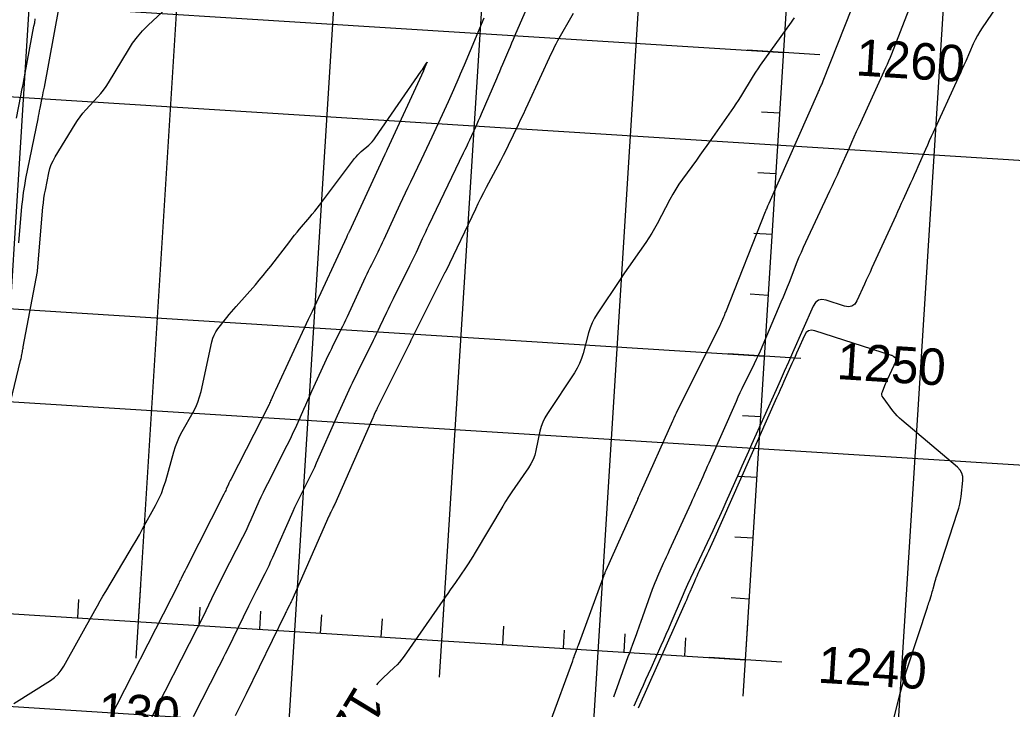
# Model space of a CAD drawing. Extents: x 658976 to 668721, y 639543 to 647196.
# Drawn here: x 661779.9 to 661943.1, y 641892.5 to 642005.8 of the extents above; entities that cross this region are included whole.
import ezdxf

# ---------------------------------------------------------------- set-up
doc = ezdxf.new("R2010")
doc.units = 0
for name, color, linetype in [('Ex_Contour Labels', 7, 'Continuous'), ('Ex_Major Contours', 7, 'Continuous'), ('Ex_Minor Contours', 7, 'Continuous'), ('R_Axis', 7, 'Continuous'), ('R_Axis Annot', 7, 'Continuous'), ('R_Grid', 7, 'Continuous')]:
    doc.layers.add(name, color=color, linetype=linetype)

msp = doc.modelspace()

# ---------------------------------------------------------------- linework, layer by layer
at = {"layer": 'Ex_Major Contours'}
for points in [[(661867.15, 641890.47), (661870.82, 641900.42), (661870.9, 641900.63), (661870.97, 641900.85), (661871.05, 641901.06), (661871.13, 641901.28), (661871.44, 641902.13), (661871.51, 641902.35), (661871.59, 641902.56), (661871.67, 641902.77), (661871.75, 641902.99), (661875.84, 641914.07), (661875.88, 641914.18), (661875.92, 641914.28), (661875.96, 641914.39), (661875.99, 641914.5), (661876.14, 641914.92), (661876.18, 641915.03), (661876.22, 641915.13), (661876.27, 641915.23), (661876.31, 641915.34), (661881.45, 641926.84), (661881.5, 641926.96), (661881.55, 641927.08), (661881.61, 641927.2), (661881.66, 641927.32), (661881.88, 641927.79), (661881.93, 641927.91), (661881.99, 641928.03), (661882.04, 641928.14), (661882.09, 641928.26), (661887.27, 641939.88), (661887.33, 641940), (661887.38, 641940.12), (661887.44, 641940.24), (661887.49, 641940.36), (661887.7, 641940.85), (661887.76, 641940.97), (661887.81, 641941.09), (661887.87, 641941.21), (661887.93, 641941.33), (661894.98, 641955.41), (661895.07, 641955.6), (661895.16, 641955.79), (661895.25, 641955.99), (661895.33, 641956.18), (661895.66, 641956.96), (661895.75, 641957.16), (661895.83, 641957.35), (661895.91, 641957.55), (661895.99, 641957.74), (661902.51, 641974.26), (661902.55, 641974.38), (661902.6, 641974.5), (661902.65, 641974.61), (661902.71, 641974.73), (661902.92, 641975.19), (661902.97, 641975.3), (661903.03, 641975.41), (661903.08, 641975.53), (661903.13, 641975.65), (661911.18, 641993.86), (661911.25, 641994.01), (661911.32, 641994.17), (661911.39, 641994.33), (661911.46, 641994.48), (661911.75, 641995.1), (661911.82, 641995.26), (661911.89, 641995.41), (661911.95, 641995.57), (661912.02, 641995.73), (661917.97, 642010.88)], [(661907.21, 642006.13), (661906.98, 642005.74), (661906.73, 642005.38), (661901.65, 641998.3), (661901.26, 641997.74), (661900.88, 641997.18), (661900.51, 641996.6), (661900.15, 641996.02), (661898.75, 641993.68), (661898.4, 641993.1), (661898.03, 641992.52), (661897.65, 641991.95), (661897.27, 641991.39), (661893.42, 641985.9), (661892.86, 641985.1), (661892.29, 641984.31), (661891.72, 641983.52), (661891.15, 641982.73), (661888.85, 641979.58), (661888.29, 641978.78), (661887.76, 641977.96), (661887.26, 641977.13), (661886.8, 641976.27), (661884.69, 641972.26), (661884.26, 641971.47), (661883.8, 641970.7), (661883.32, 641969.94), (661882.82, 641969.19), (661880.75, 641966.24), (661880.24, 641965.5), (661879.73, 641964.75), (661879.22, 641964.01), (661878.71, 641963.26), (661874.83, 641957.47), (661874.38, 641956.73), (661873.99, 641955.96), (661873.67, 641955.16), (661873.41, 641954.32), (661872.52, 641950.93), (661872.27, 641950.1), (661871.95, 641949.3), (661871.56, 641948.52), (661871.11, 641947.78), (661866.65, 641941.07), (661866.24, 641940.39), (661865.9, 641939.67), (661865.63, 641938.93), (661865.43, 641938.16), (661864.77, 641935.02), (661864.57, 641934.25), (661864.3, 641933.51), (661863.95, 641932.8), (661863.53, 641932.13), (661861.29, 641928.93), (661860.78, 641928.18), (661860.27, 641927.41), (661859.78, 641926.64), (661859.31, 641925.85), (661854.78, 641918.23), (661854.4, 641917.6), (661854, 641916.97), (661853.6, 641916.35), (661853.19, 641915.74), (661851.52, 641913.3), (661851.1, 641912.69), (661850.68, 641912.09), (661850.26, 641911.48), (661849.84, 641910.87), (661843.11, 641901.19), (661842.74, 641900.69), (661842.35, 641900.22), (661841.93, 641899.76), (661841.48, 641899.33), (661839.64, 641897.66), (661839.2, 641897.22), (661838.79, 641896.76), (661838.58, 641896.47)], [(661923.17, 641889.22), (661924.65, 641895.06), (661924.97, 641896.26), (661925.3, 641897.44), (661925.66, 641898.63), (661926.03, 641899.8), (661929.13, 641909.25), (661929.21, 641909.5), (661929.29, 641909.75), (661929.38, 641910.01), (661929.46, 641910.26), (661929.79, 641911.27), (661929.87, 641911.52), (661929.94, 641911.78), (661930.02, 641912.03), (661930.09, 641912.29), (661930.43, 641913.54), (661930.52, 641913.83), (661930.6, 641914.13), (661930.69, 641914.42), (661930.78, 641914.71), (661934.11, 641924.89), (661934.3, 641925.52), (661934.45, 641926.16), (661934.58, 641926.8), (661934.67, 641927.46), (661934.96, 641930.08), (661934.96, 641930.7), (661934.82, 641931.27), (661934.53, 641931.78), (661934.1, 641932.24), (661924.95, 641939.96), (661924.55, 641940.32), (661924.17, 641940.7), (661923.81, 641941.1), (661923.47, 641941.53), (661921.85, 641943.69), (661921.72, 641943.92), (661921.66, 641944.15), (661921.66, 641944.4), (661921.73, 641944.65), (661922.15, 641945.67), (661922.26, 641945.93), (661922.37, 641946.18), (661922.48, 641946.44), (661922.59, 641946.69), (661924.01, 641949.75), (661924.04, 641949.85), (661924.04, 641949.94), (661924, 641950.03), (661923.94, 641950.11), (661923.6, 641950.41), (661923.51, 641950.48), (661923.42, 641950.54), (661923.32, 641950.59), (661923.21, 641950.62), (661910.63, 641954.66), (661910.07, 641954.75), (661909.6, 641954.66), (661909.21, 641954.37), (661908.92, 641953.89), (661907.89, 641951.58), (661907.64, 641951.01), (661907.38, 641950.43), (661907.13, 641949.85), (661906.87, 641949.28), (661905.55, 641946.35), (661905.25, 641945.67), (661904.94, 641944.99), (661904.64, 641944.31), (661904.34, 641943.63), (661893.97, 641920.26), (661893.7, 641919.66), (661893.43, 641919.07), (661893.16, 641918.48), (661892.88, 641917.89), (661891.61, 641915.21), (661891.41, 641914.78), (661891.21, 641914.35), (661891.02, 641913.91), (661890.83, 641913.48), (661890.07, 641911.73), (661889.88, 641911.3), (661889.69, 641910.86), (661889.5, 641910.42), (661889.31, 641909.99), (661881.58, 641892.67)]]:
    msp.add_lwpolyline(points, dxfattribs=at)
at = {"layer": 'Ex_Minor Contours'}
for points in [[(661776.99, 641937.25), (661780.04, 641949.77), (661780.08, 641949.96), (661780.12, 641950.14), (661780.16, 641950.33), (661780.2, 641950.52), (661780.33, 641951.27), (661780.37, 641951.45), (661780.4, 641951.64), (661780.44, 641951.83), (661780.47, 641952.01), (661782.82, 641964.43), (661782.83, 641964.45), (661782.83, 641964.47), (661782.83, 641964.49), (661782.84, 641964.5), (661783.72, 641974.98), (661783.79, 641975.69), (661783.88, 641976.4), (661783.99, 641977.11), (661784.13, 641977.81), (661784.69, 641980.63), (661784.87, 641981.32), (661785.09, 641981.99), (661785.38, 641982.63), (661785.72, 641983.26), (661789, 641988.63), (661789.39, 641989.25), (661789.82, 641989.84), (661790.27, 641990.41), (661790.75, 641990.96), (661792.74, 641993.11), (661793.23, 641993.66), (661793.68, 641994.23), (661794.1, 641994.83), (661794.5, 641995.44), (661797.76, 642000.87), (661798.46, 642001.96), (661799.24, 642002.99), (661800.08, 642003.96), (661800.99, 642004.88), (661808.68, 642012.07)], [(661863.69, 642008.72), (661861.27, 642003.11), (661861.02, 642002.52), (661860.77, 642001.94), (661860.52, 642001.35), (661860.27, 642000.76), (661859.27, 641998.41), (661859.02, 641997.82), (661858.77, 641997.23), (661858.52, 641996.65), (661858.27, 641996.06), (661855.76, 641990.26), (661855.53, 641989.72), (661855.29, 641989.19), (661855.05, 641988.65), (661854.81, 641988.12), (661853.82, 641985.99), (661853.58, 641985.45), (661853.33, 641984.92), (661853.08, 641984.39), (661852.83, 641983.86), (661847.12, 641971.96), (661846.85, 641971.41), (661846.59, 641970.86), (661846.34, 641970.31), (661846.08, 641969.76), (661845.06, 641967.55), (661844.8, 641967), (661844.54, 641966.45), (661844.27, 641965.9), (661844, 641965.36), (661841.29, 641959.95), (661841.01, 641959.38), (661840.73, 641958.81), (661840.46, 641958.23), (661840.19, 641957.66), (661839.12, 641955.36), (661838.85, 641954.78), (661838.58, 641954.21), (661838.3, 641953.64), (661838.02, 641953.07), (661835.42, 641947.87), (661835.13, 641947.28), (661834.84, 641946.69), (661834.56, 641946.09), (661834.28, 641945.5), (661833.17, 641943.11), (661832.89, 641942.51), (661832.62, 641941.91), (661832.35, 641941.31), (661832.09, 641940.71), (661828.64, 641932.89), (661828.34, 641932.22), (661828.03, 641931.55), (661827.71, 641930.89), (661827.38, 641930.24), (661826.05, 641927.62), (661825.72, 641926.97), (661825.4, 641926.3), (661825.09, 641925.64), (661824.79, 641924.97), (661821.46, 641917.42), (661821.15, 641916.74), (661820.83, 641916.06), (661820.51, 641915.39), (661820.17, 641914.72), (661818.82, 641912.06), (661818.48, 641911.4), (661818.15, 641910.73), (661817.82, 641910.06), (661817.49, 641909.39), (661814.03, 641902.29), (661813.69, 641901.59), (661813.34, 641900.9), (661813, 641900.2), (661812.64, 641899.51), (661808.43, 641891.24)], [(661941.31, 642009.17), (661938.14, 642004.48), (661937.73, 642003.84), (661937.35, 642003.18), (661936.99, 642002.51), (661936.67, 642001.81), (661935.44, 641999.01), (661935.13, 641998.31), (661934.82, 641997.61), (661934.51, 641996.91), (661934.19, 641996.22), (661930.08, 641987.27), (661929.76, 641986.58), (661929.45, 641985.88), (661929.14, 641985.18), (661928.83, 641984.48), (661927.57, 641981.61), (661927.28, 641980.94), (661926.98, 641980.27), (661926.67, 641979.6), (661926.37, 641978.93), (661925.14, 641976.25), (661924.84, 641975.58), (661924.53, 641974.91), (661924.23, 641974.24), (661923.92, 641973.57), (661920.01, 641965), (661919.7, 641964.33), (661919.4, 641963.66), (661919.09, 641962.98), (661918.78, 641962.31), (661917.55, 641959.62), (661917.19, 641959.05), (661916.73, 641958.72), (661916.18, 641958.61), (661915.52, 641958.72), (661912.49, 641959.69), (661911.8, 641959.81), (661911.22, 641959.69), (661910.75, 641959.34), (661910.38, 641958.74), (661906.97, 641951.03), (661906.29, 641949.51), (661905.61, 641947.99), (661904.94, 641946.47), (661904.26, 641944.95), (661900.23, 641935.99), (661899.7, 641934.81), (661899.18, 641933.62), (661898.65, 641932.44), (661898.12, 641931.26), (661896.02, 641926.52), (661895.49, 641925.34), (661894.95, 641924.16), (661894.41, 641922.98), (661893.86, 641921.81), (661890.65, 641915.04), (661890.18, 641914.03), (661889.71, 641913), (661889.25, 641911.98), (661888.8, 641910.95), (661886.94, 641906.63), (661886.54, 641905.7), (661886.13, 641904.76), (661885.72, 641903.83), (661885.3, 641902.9), (661883.64, 641899.18), (661883.22, 641898.25), (661882.81, 641897.31), (661882.39, 641896.38), (661881.97, 641895.45), (661880.87, 641892.99)], [(661779.76, 641969.13), (661780.26, 641975.08), (661780.38, 641976.25), (661780.52, 641977.4), (661780.71, 641978.56), (661780.92, 641979.7), (661782.91, 641989.51), (661782.99, 641989.94), (661783.08, 641990.37), (661783.17, 641990.81), (661783.25, 641991.24), (661783.6, 641992.98), (661783.69, 641993.41), (661783.77, 641993.85), (661783.86, 641994.28), (661783.94, 641994.72), (661786.35, 642007.56)], [(661870.88, 642006.84), (661868.34, 642002.31), (661868.06, 642001.8), (661867.79, 642001.28), (661867.53, 642000.76), (661867.28, 642000.23), (661863.45, 641991.93), (661863.06, 641991.07), (661862.66, 641990.22), (661862.25, 641989.37), (661861.85, 641988.53), (661860.21, 641985.14), (661859.8, 641984.3), (661859.38, 641983.46), (661858.95, 641982.62), (661858.51, 641981.79), (661856.6, 641978.2), (661856.14, 641977.32), (661855.68, 641976.44), (661855.24, 641975.55), (661854.81, 641974.66), (661849.93, 641964.49), (661849.92, 641964.47), (661849.91, 641964.45), (661849.9, 641964.43), (661849.89, 641964.4), (661849.85, 641964.31), (661849.84, 641964.29), (661849.83, 641964.27), (661849.82, 641964.25), (661849.81, 641964.23), (661844.32, 641953.29), (661844.28, 641953.22), (661844.24, 641953.14), (661844.21, 641953.06), (661844.17, 641952.98), (661844.02, 641952.66), (661843.98, 641952.58), (661843.95, 641952.5), (661843.91, 641952.42), (661843.87, 641952.34), (661838.66, 641941.93), (661838.6, 641941.8), (661838.54, 641941.67), (661838.47, 641941.54), (661838.41, 641941.41), (661838.17, 641940.89), (661838.11, 641940.76), (661838.05, 641940.62), (661837.99, 641940.49), (661837.93, 641940.36), (661831.68, 641926.17), (661831.61, 641926.01), (661831.53, 641925.84), (661831.45, 641925.68), (661831.37, 641925.52), (661831.04, 641924.87), (661830.96, 641924.7), (661830.88, 641924.54), (661830.8, 641924.38), (661830.73, 641924.21), (661824.61, 641910.34), (661824.52, 641910.15), (661824.44, 641909.97), (661824.35, 641909.78), (661824.25, 641909.6), (661823.88, 641908.87), (661823.79, 641908.68), (661823.7, 641908.5), (661823.61, 641908.32), (661823.52, 641908.13), (661817.13, 641895.02), (661817.02, 641894.79), (661816.91, 641894.56), (661816.79, 641894.34), (661816.68, 641894.11), (661815.3, 641891.41)], [(661877.57, 641894.49), (661879.96, 641901.14), (661880.13, 641901.62), (661880.3, 641902.09), (661880.48, 641902.56), (661880.65, 641903.03), (661881.35, 641904.92), (661881.52, 641905.39), (661881.69, 641905.87), (661881.86, 641906.34), (661882.03, 641906.81), (661883.95, 641912.19), (661884.15, 641912.74), (661884.37, 641913.28), (661884.59, 641913.82), (661884.82, 641914.36), (661885.77, 641916.49), (661886.01, 641917.02), (661886.25, 641917.55), (661886.49, 641918.09), (661886.73, 641918.62), (661890.28, 641926.32), (661890.53, 641926.87), (661890.78, 641927.43), (661891.03, 641927.98), (661891.28, 641928.53), (661892.26, 641930.74), (661892.51, 641931.29), (661892.75, 641931.85), (661893, 641932.4), (661893.24, 641932.95), (661897.73, 641943.12), (661898.04, 641943.82), (661898.36, 641944.51), (661898.69, 641945.2), (661899.03, 641945.88), (661900.4, 641948.61), (661900.73, 641949.3), (661901.06, 641949.99), (661901.37, 641950.68), (661901.68, 641951.38), (661905.11, 641959.43), (661905.45, 641960.24), (661905.79, 641961.06), (661906.12, 641961.87), (661906.45, 641962.69), (661907.74, 641965.98), (661908.07, 641966.8), (661908.42, 641967.61), (661908.77, 641968.42), (661909.14, 641969.22), (661913.12, 641977.68), (661913.53, 641978.56), (661913.93, 641979.44), (661914.33, 641980.33), (661914.73, 641981.21), (661916.3, 641984.76), (661916.69, 641985.65), (661917.09, 641986.53), (661917.49, 641987.42), (661917.89, 641988.3), (661922.31, 641997.93), (661922.57, 641998.49), (661922.82, 641999.06), (661923.05, 641999.64), (661923.29, 642000.21), (661926.15, 642007.51)], [(661779.34, 641989.61), (661780.08, 641993.31), (661780.26, 641994.24), (661780.44, 641995.17), (661780.62, 641996.09), (661780.8, 641997.02), (661782.24, 642004.71), (661782.35, 642005.31), (661782.44, 642005.92)], [(661856.22, 642006.03), (661852.96, 641998.34), (661852.75, 641997.83), (661852.53, 641997.33), (661852.31, 641996.82), (661852.1, 641996.32), (661851.22, 641994.29), (661851, 641993.79), (661850.78, 641993.28), (661850.55, 641992.78), (661850.33, 641992.28), (661847.65, 641986.48), (661847.22, 641985.55), (661846.79, 641984.63), (661846.35, 641983.71), (661845.91, 641982.79), (661844.15, 641979.12), (661843.71, 641978.2), (661843.28, 641977.27), (661842.84, 641976.35), (661842.41, 641975.43), (661839.75, 641969.67), (661839.51, 641969.15), (661839.26, 641968.62), (661839.01, 641968.1), (661838.75, 641967.59), (661837.71, 641965.52), (661837.46, 641965), (661837.2, 641964.48), (661836.96, 641963.96), (661836.71, 641963.44), (661833.72, 641956.98), (661833.47, 641956.44), (661833.22, 641955.91), (661832.96, 641955.39), (661832.7, 641954.86), (661831.65, 641952.76), (661831.39, 641952.24), (661831.14, 641951.71), (661830.88, 641951.18), (661830.63, 641950.65), (661827.87, 641944.69), (661827.53, 641943.95), (661827.19, 641943.21), (661826.86, 641942.46), (661826.53, 641941.72), (661825.21, 641938.74), (661824.88, 641937.99), (661824.54, 641937.26), (661824.18, 641936.52), (661823.82, 641935.8), (661820.62, 641929.53), (661820.26, 641928.81), (661819.91, 641928.07), (661819.56, 641927.34), (661819.23, 641926.6), (661817.92, 641923.63), (661817.59, 641922.89), (661817.24, 641922.15), (661816.89, 641921.42), (661816.53, 641920.7), (661813.31, 641914.38), (661812.95, 641913.67), (661812.59, 641912.96), (661812.24, 641912.25), (661811.89, 641911.53), (661810.49, 641908.66), (661810.14, 641907.94), (661809.79, 641907.23), (661809.43, 641906.52), (661809.07, 641905.8), (661801.13, 641890.23)], [(661778.94, 641893.42), (661784.93, 641897.21), (661785.6, 641897.7), (661786.2, 641898.25), (661786.72, 641898.88), (661787.17, 641899.58), (661792.24, 641908.71), (661792.67, 641909.49), (661793.12, 641910.27), (661793.57, 641911.04), (661794.03, 641911.82), (661797.9, 641918.29), (661798.46, 641919.24), (661799.02, 641920.19), (661799.56, 641921.15), (661800.1, 641922.11), (661802.23, 641925.96), (661802.73, 641926.94), (661803.18, 641927.94), (661803.56, 641928.96), (661803.89, 641930.01), (661805.22, 641934.76), (661805.49, 641935.63), (661805.81, 641936.48), (661806.19, 641937.31), (661806.61, 641938.12), (661808.41, 641941.31), (661808.83, 641942.12), (661809.18, 641942.96), (661809.47, 641943.82), (661809.7, 641944.7), (661811.49, 641952.88), (661811.65, 641953.44), (661811.86, 641953.98), (661812.14, 641954.5), (661812.48, 641954.98), (661813.96, 641956.86), (661814.33, 641957.33), (661814.71, 641957.79), (661815.09, 641958.24), (661815.49, 641958.69), (661818.64, 641962.25), (661819.29, 641962.99), (661819.93, 641963.75), (661820.55, 641964.52), (661821.16, 641965.3), (661824.29, 641969.37), (661824.68, 641969.88), (661825.09, 641970.38), (661825.49, 641970.88), (661825.91, 641971.37), (661827.59, 641973.32), (661828, 641973.82), (661828.41, 641974.31), (661828.81, 641974.82), (661829.2, 641975.33), (661834.95, 641982.96), (661835.2, 641983.28), (661835.47, 641983.58), (661835.75, 641983.86), (661836.05, 641984.13), (661837.28, 641985.19), (661837.57, 641985.46), (661837.85, 641985.75), (661838.11, 641986.05), (661838.35, 641986.38), (661845.9, 641997.35), (661845.92, 641997.38), (661845.93, 641997.4), (661845.95, 641997.42), (661845.97, 641997.44), (661846.05, 641997.52), (661846.07, 641997.54), (661846.09, 641997.56), (661846.1, 641997.58), (661846.12, 641997.6), (661846.75, 641998.65), (661846.83, 641998.79), (661846.87, 641998.83), (661846.86, 641998.78), (661846.8, 641998.63), (661846.3, 641997.43), (661846.29, 641997.41), (661846.28, 641997.39), (661846.27, 641997.37), (661840.33, 641984.49), (661840.29, 641984.41), (661840.26, 641984.33), (661840.22, 641984.25), (661840.18, 641984.17), (661840.03, 641983.85), (661839.99, 641983.77), (661839.95, 641983.69), (661839.91, 641983.61), (661839.88, 641983.53), (661834.07, 641970.96), (661834.03, 641970.88), (661833.99, 641970.8), (661833.95, 641970.72), (661833.91, 641970.64), (661833.75, 641970.32), (661833.71, 641970.24), (661833.67, 641970.16), (661833.64, 641970.08), (661833.6, 641970), (661827.97, 641957.84), (661827.92, 641957.73), (661827.86, 641957.62), (661827.81, 641957.51), (661827.76, 641957.4), (661827.54, 641956.96), (661827.48, 641956.85), (661827.43, 641956.73), (661827.37, 641956.62), (661827.32, 641956.51), (661821.93, 641944.89), (661821.84, 641944.69), (661821.75, 641944.5), (661821.67, 641944.31), (661821.58, 641944.11), (661821.24, 641943.34), (661821.15, 641943.14), (661821.06, 641942.95), (661820.97, 641942.76), (661820.88, 641942.57), (661814.59, 641930.25), (661814.49, 641930.05), (661814.4, 641929.85), (661814.3, 641929.65), (661814.21, 641929.45), (661813.85, 641928.64), (661813.76, 641928.44), (661813.67, 641928.24), (661813.57, 641928.04), (661813.47, 641927.84), (661807.24, 641915.6), (661807.13, 641915.4), (661807.03, 641915.19), (661806.93, 641914.99), (661806.83, 641914.78), (661806.43, 641913.97), (661806.33, 641913.76), (661806.23, 641913.56), (661806.13, 641913.36), (661806.03, 641913.15), (661793.29, 641888.14)]]:
    msp.add_lwpolyline(points, dxfattribs=at)
at = {"layer": 'R_Axis'}
for p, q in [((661899.22, 641900.61), (661911.75, 642100.21)), ((661911.47, 642000.03), (661899.5, 642000.79)), ((660402.17, 641994.63), (661899.22, 641900.61)), ((661904.86, 641990.43), (661901.87, 641990.62)), ((661904.23, 641980.45), (661901.24, 641980.64)), ((661903.61, 641970.47), (661900.61, 641970.66)), ((661902.98, 641960.49), (661899.98, 641960.68)), ((661908.34, 641950.13), (661896.36, 641950.88)), ((661901.73, 641940.53), (661898.73, 641940.72)), ((661901.1, 641930.55), (661898.1, 641930.74)), ((661900.47, 641920.57), (661897.48, 641920.75)), ((661799.04, 641900.89), (661799.79, 641912.86)), ((661789.43, 641907.5), (661789.62, 641910.5)), ((661899.84, 641910.59), (661896.85, 641910.77)), ((661809.39, 641906.25), (661809.58, 641909.24)), ((661819.38, 641905.62), (661819.56, 641908.61)), ((661848.94, 641897.75), (661849.69, 641909.73)), ((661829.36, 641904.99), (661829.54, 641907.99)), ((661839.34, 641904.37), (661839.52, 641907.36)), ((661859.3, 641903.11), (661859.48, 641906.11)), ((661869.28, 641902.49), (661869.47, 641905.48)), ((661898.84, 641894.62), (661899.59, 641906.59)), ((661879.26, 641901.86), (661879.45, 641904.85)), ((661889.24, 641901.23), (661889.43, 641904.23)), ((661905.21, 641900.23), (661893.23, 641900.98))]:
    msp.add_line(p, q, dxfattribs=at)
at = {"layer": 'R_Grid'}
for p, q in [((661799.41, 641906.87), (661811.95, 642106.48)), ((661849.32, 641903.74), (661861.85, 642103.35)), ((661899.22, 641900.61), (661911.75, 642100.21)), ((660408.44, 642094.43), (661905.49, 642000.41)), ((661771.13, 641843.29), (661786.81, 642092.79)), ((661821.04, 641840.15), (661836.71, 642089.66)), ((661870.94, 641837.02), (661886.61, 642086.53)), ((661920.84, 641833.88), (661936.51, 642083.39)), ((660405.3, 642044.53), (661902.35, 641950.51)), ((661630.83, 642002.39), (663127.88, 641908.37)), ((660402.17, 641994.63), (661899.22, 641900.61)), ((661627.7, 641952.49), (663124.75, 641858.47)), ((661624.56, 641902.59), (663121.61, 641808.57))]:
    msp.add_line(p, q, dxfattribs=at)

# ---------------------------------------------------------------- texts
at = {"layer": 'Ex_Contour Labels'}
msp.add_text('1255', height=6, rotation=238.8305, dxfattribs=at).set_placement((661835.15, 641896.6))
at = {"layer": 'R_Axis Annot'}
for s, p in [('1260', (661917.27, 641996.66)), ('1250', (661914.14, 641946.76)), ('1240', (661911.01, 641896.86)), ('130', (661792.65, 641889.26))]:
    msp.add_text(s, height=6, rotation=356.4063, dxfattribs=at).set_placement(p)

doc.saveas('drawing.dxf')
